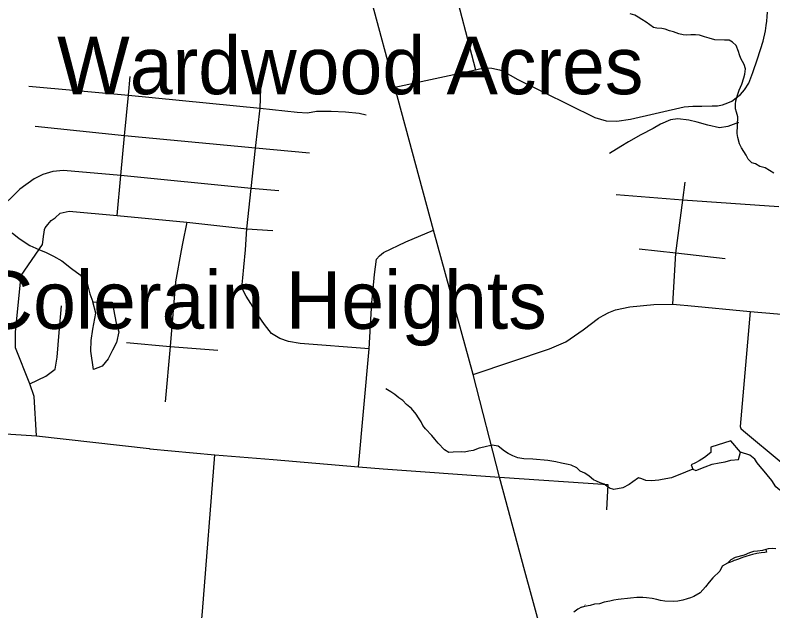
# Model space of a CAD drawing. Extents: x 0 to 69.5, y -4.5 to 22.
# Drawn here: x 3.515 to 4.554, y 16.285 to 17.102 of the extents above; entities that cross this region are included whole.
import ezdxf

# ---------------------------------------------------------------- set-up
doc = ezdxf.new("R2010")
doc.units = 0
for name, color, linetype in [('GM_X_County_Road', 7, 'Continuous'), ('GM_X_Minor_Lake', 7, 'Continuous'), ('GM_X_Minor_River', 7, 'Continuous'), ('GM_X_Township_Subdivision', 7, 'Continuous'), ('GM_X_Unincorporated_Text', 7, 'Continuous'), ('GM_X_US_Route', 7, 'Continuous')]:
    doc.layers.add(name, color=color, linetype=linetype)

msp = doc.modelspace()

# ---------------------------------------------------------------- linework, layer by layer
at = {"layer": 'GM_X_County_Road'}
for points in [[(4.1431, 16.6089), (4.2477, 16.644), (4.27, 16.6535), (4.294, 16.6701), (4.3151, 16.6862), (4.3212, 16.6898), (4.3294, 16.6938), (4.3383, 16.6974), (4.3582, 16.7015), (4.3907, 16.7048), (4.417, 16.7053), (4.427, 16.7043), (4.4376, 16.7033), (4.5229, 16.6954), (4.6194, 16.6869)], [(3.0077, 16.6072), (3.0199, 16.6034), (3.2263, 16.5685), (3.2928, 16.5595), (3.3237, 16.5541), (3.3826, 16.5464), (3.4363, 16.5348), (3.4732, 16.5304), (3.5089, 16.527), (3.5443, 16.5245), (3.6987, 16.5072), (3.6996, 16.5071)], [(3.6996, 16.5071), (3.7888, 16.4987), (3.8689, 16.4921)], [(3.6274, 15.5008), (3.6334, 15.5983), (3.6428, 15.6844), (3.6442, 15.6947), (3.6526, 15.7123), (3.6907, 15.7752), (3.6948, 15.7884), (3.6964, 15.8066), (3.7002, 15.8416), (3.7057, 15.8918), (3.7083, 15.9035), (3.7269, 15.9403), (3.7414, 15.9828), (3.7462, 16.0207), (3.7514, 16.0744), (3.7681, 16.2443), (3.7721, 16.2837), (3.7888, 16.4987)], [(3.8689, 16.4921), (3.869, 16.4921), (3.986, 16.4824), (4.0195, 16.4796), (4.1794, 16.4679)]]:
    msp.add_lwpolyline(points, dxfattribs=at)
at = {"layer": 'GM_X_Minor_Lake'}
for points in [[(3.6224, 16.6158), (3.6187, 16.6406), (3.6194, 16.6554), (3.6216, 16.6709), (3.6255, 16.6928), (3.6218, 16.7084)], [(3.6218, 16.7084), (3.6479, 16.7079), (3.6534, 16.6793), (3.6573, 16.6674), (3.6539, 16.6527), (3.6487, 16.6422), (3.6424, 16.6302), (3.6342, 16.6201), (3.6223, 16.6158)], [(4.5098, 16.5021), (4.4963, 16.5177), (4.4692, 16.5092), (4.469, 16.502), (4.4605, 16.495), (4.4532, 16.4906), (4.4482, 16.4877), (4.442, 16.4848), (4.4446, 16.479), (4.4483, 16.4774), (4.4613, 16.4821), (4.4709, 16.486), (4.4805, 16.4877), (4.4888, 16.489), (4.4965, 16.4912)], [(4.4965, 16.4912), (4.507, 16.4921), (4.5098, 16.5021)]]:
    msp.add_lwpolyline(points, dxfattribs=at)
at = {"layer": 'GM_X_Minor_River'}
for points in [[(4.5556, 16.8851), (4.5436, 16.8923), (4.5364, 16.8941), (4.5304, 16.8977), (4.5255, 16.8993), (4.5203, 16.904), (4.5175, 16.9098), (4.5109, 16.9195), (4.5084, 16.9253), (4.5063, 16.9337), (4.5053, 16.9391), (4.506, 16.9623), (4.5042, 16.9685), (4.5028, 16.9731), (4.503, 16.9795), (4.5035, 16.9841), (4.5056, 16.992), (4.5081, 16.9988), (4.5114, 17.0071), (4.5143, 17.0158), (4.5159, 17.0207), (4.5165, 17.0279), (4.5147, 17.034), (4.5104, 17.0422), (4.5083, 17.0472), (4.5072, 17.0518), (4.504, 17.0602), (4.4988, 17.0646), (4.4944, 17.0674), (4.4879, 17.0672), (4.4746, 17.0679), (4.467, 17.07), (4.4602, 17.0717), (4.4535, 17.0742), (4.4482, 17.0747), (4.4417, 17.0745), (4.4356, 17.0743), (4.431, 17.0745), (4.425, 17.0762), (4.4178, 17.0786), (4.4126, 17.0803), (4.4065, 17.0824), (4.402, 17.0833), (4.3952, 17.0838), (4.3906, 17.0847), (4.3806, 17.0919), (4.3746, 17.0958), (4.3693, 17.0987), (4.3648, 17.1014), (4.3584, 17.1035)], [(4.5057, 16.9543), (4.5072, 16.9546), (4.4926, 16.9489), (4.4808, 16.9469), (4.4649, 16.9507), (4.4502, 16.9548), (4.4388, 16.9574), (4.4237, 16.9593), (4.4138, 16.958), (4.3999, 16.9519), (4.3899, 16.9464), (4.373, 16.9373), (4.356, 16.9278), (4.3456, 16.9216), (4.3302, 16.9117)], [(3.5109, 16.8032), (3.5206, 16.7953), (3.5352, 16.7859), (3.5476, 16.7802), (3.5574, 16.7762), (3.5675, 16.771), (3.5791, 16.7646), (3.5922, 16.754), (3.6041, 16.7454), (3.6141, 16.7322), (3.6176, 16.7196), (3.6218, 16.7084)], [(4.4446, 16.479), (4.4342, 16.475), (4.4149, 16.4671), (4.4023, 16.4648), (4.3977, 16.4638), (4.3878, 16.4629), (4.3799, 16.4635), (4.3746, 16.4656), (4.3701, 16.4669), (4.3619, 16.4618), (4.3569, 16.4581), (4.3484, 16.4534), (4.3362, 16.4511), (4.3301, 16.4531), (4.323, 16.4583), (4.3174, 16.4603), (4.3125, 16.4624), (4.308, 16.4644), (4.3024, 16.4695), (4.2961, 16.4735), (4.2901, 16.4763), (4.2853, 16.481), (4.2777, 16.4843), (4.2732, 16.4852), (4.2645, 16.4873), (4.2566, 16.4891), (4.2456, 16.4909), (4.2251, 16.4926), (4.2126, 16.4934), (4.2042, 16.4947), (4.1975, 16.4972), (4.1911, 16.5004), (4.1862, 16.5036), (4.1773, 16.5107), (4.169, 16.5121), (4.1579, 16.5094), (4.1514, 16.5076), (4.1433, 16.5048), (4.1372, 16.5035), (4.1314, 16.5025), (4.1269, 16.5026), (4.1158, 16.5022), (4.1097, 16.5019), (4.1038, 16.5055), (4.0953, 16.5145), (4.0908, 16.52), (4.0864, 16.5251), (4.0779, 16.5344), (4.0743, 16.5391), (4.0717, 16.5441), (4.0684, 16.5492), (4.0652, 16.5546), (4.0585, 16.562), (4.0518, 16.5679), (4.0466, 16.573), (4.0411, 16.577), (4.0355, 16.5813), (4.0302, 16.5849), (4.0235, 16.5893)], [(4.6349, 16.4612), (4.6183, 16.4634), (4.6087, 16.4591), (4.5991, 16.4555), (4.5925, 16.4527), (4.5845, 16.4506), (4.576, 16.4482), (4.5692, 16.4495), (4.5635, 16.45), (4.5583, 16.4548), (4.5529, 16.4633), (4.5462, 16.4711), (4.5422, 16.4762), (4.5367, 16.4828), (4.5326, 16.4878), (4.5293, 16.4925), (4.5226, 16.498), (4.5097, 16.5022)], [(4.5443, 16.3688), (4.5455, 16.365), (4.543, 16.3647), (4.5382, 16.3641), (4.532, 16.3633), (4.5263, 16.3621), (4.5229, 16.3612), (4.5171, 16.3593), (4.5125, 16.3579), (4.5092, 16.3567), (4.5056, 16.3552), (4.5027, 16.354), (4.5012, 16.3536), (4.4985, 16.3524), (4.496, 16.3514), (4.4935, 16.3505), (4.4921, 16.3499)], [(4.54, 16.3677), (4.5331, 16.3667), (4.5274, 16.3661), (4.5221, 16.3644), (4.5147, 16.3612), (4.5025, 16.3577), (4.4967, 16.3548), (4.4921, 16.3499)], [(4.5443, 16.3688), (4.54, 16.3677)], [(4.5583, 16.3698), (4.553, 16.37), (4.5477, 16.3698), (4.5443, 16.3688)], [(4.4921, 16.3499), (4.4847, 16.346), (4.4814, 16.3392), (4.4717, 16.33), (4.4666, 16.324), (4.4618, 16.3177), (4.4544, 16.3095), (4.4459, 16.3044), (4.4413, 16.3027), (4.4367, 16.3013), (4.4305, 16.2995), (4.424, 16.2982), (4.4183, 16.2976), (4.4058, 16.2979), (4.4001, 16.2989), (4.3948, 16.3001), (4.3884, 16.3018), (4.3808, 16.3024), (4.3759, 16.303), (4.3675, 16.3032), (4.3587, 16.3023), (4.342, 16.3005), (4.3362, 16.2995), (4.3305, 16.2978), (4.3228, 16.2968), (4.3163, 16.2943), (4.3095, 16.2938), (4.3037, 16.292), (4.2957, 16.2907), (4.2913, 16.2894)], [(4.2965, 16.293), (4.2966, 16.2923)], [(4.2917, 16.2899), (4.2868, 16.2868), (4.281, 16.2831)]]:
    msp.add_lwpolyline(points, dxfattribs=at)
at = {"layer": 'GM_X_Township_Subdivision'}
for points in [[(4.2504, 17.246), (4.2399, 17.2463), (4.2209, 17.2479), (4.2, 17.2504), (4.1444, 17.2619), (4.1342, 17.2617), (4.1233, 17.2587), (4.1133, 17.2519), (4.1072, 17.2448), (4.1016, 17.2378), (4.098, 17.2281), (4.0972, 17.2166), (4.1007, 17.2009), (4.1059, 17.1806), (4.1093, 17.1652), (4.1138, 17.1512), (4.1464, 17.0268)], [(4.5267, 17.0228), (4.5332, 17.0419), (4.5407, 17.066), (4.5441, 17.0801), (4.5451, 17.0873), (4.5458, 17.0934), (4.5465, 17.0999), (4.5469, 17.1055)], [(4.0359, 17.0028), (4.1464, 17.0268), (4.1519, 17.0281)], [(4.1519, 17.0281), (4.1588, 17.0296), (4.162, 17.0296), (4.1688, 17.0289), (4.1794, 17.0268), (4.1835, 17.0251), (4.2044, 17.0136), (4.31, 16.9611), (4.3256, 16.9565), (4.3403, 16.9561), (4.3591, 16.9591), (4.4325, 16.9761), (4.4446, 16.9767), (4.4568, 16.9769), (4.4711, 16.9771), (4.4782, 16.9773), (4.4849, 16.9788), (4.4925, 16.9813), (4.498, 16.9837), (4.5039, 16.9882), (4.5096, 16.993), (4.5154, 16.9992), (4.5212, 17.0085), (4.5267, 17.0228)], [(3.6551, 16.8268), (3.6602, 16.8815), (3.6648, 16.9362), (3.6704, 16.9918), (3.6728, 17.0173)], [(3.5337, 17.0043), (3.6704, 16.9918), (3.851, 16.9739), (3.9019, 16.9687), (3.9161, 16.9677), (3.9282, 16.9699), (3.9484, 16.9699), (3.968, 16.969), (3.9869, 16.9674), (3.9965, 16.9649)], [(4.0003, 16.6438), (3.9059, 16.6515), (3.8901, 16.6543), (3.878, 16.658), (3.8668, 16.6649), (3.8569, 16.6776), (3.8426, 16.6978), (3.8383, 16.7064), (3.8317, 16.7164), (3.8261, 16.7279), (3.8274, 16.7415), (3.8286, 16.7561), (3.8308, 16.78), (3.8327, 16.8085), (3.8386, 16.8639), (3.8445, 16.9193), (3.851, 16.9739), (3.8519, 17.0009)], [(3.9186, 16.9122), (3.8445, 16.9193), (3.6648, 16.9362), (3.5425, 16.9491)], [(3.8766, 16.8608), (3.8386, 16.8639), (3.6602, 16.8815), (3.5812, 16.8884), (3.5665, 16.887), (3.553, 16.8832), (3.541, 16.877), (3.5216, 16.8628), (3.4605, 16.8035), (3.4221, 16.7604), (3.3897, 16.7285), (3.3838, 16.7214), (3.3793, 16.711), (3.3779, 16.6956), (3.3748, 16.6696), (3.3712, 16.6447), (3.371, 16.6339), (3.3731, 16.6233), (3.3815, 16.607), (3.3861, 16.5965), (3.388, 16.5857), (3.3826, 16.5464)], [(4.417, 16.7053), (4.421, 16.7752), (4.4308, 16.8481), (4.434, 16.8724)], [(4.5621, 16.8386), (4.4308, 16.8481), (4.3393, 16.855)], [(3.5546, 16.8011), (3.555, 16.8037), (3.5553, 16.8076), (3.5562, 16.8098), (3.5597, 16.8147), (3.5644, 16.8199), (3.5698, 16.8235), (3.5769, 16.8299), (3.5893, 16.833), (3.6551, 16.8268), (3.7507, 16.8176), (3.8327, 16.8085), (3.8684, 16.8061)], [(3.7507, 16.8176), (3.7446, 16.7885)], [(4.0044, 16.7081), (4.0046, 16.7116), (4.0079, 16.7459), (4.0104, 16.7671), (4.0145, 16.7716), (4.02, 16.7762), (4.0507, 16.7906), (4.0889, 16.8066)], [(3.5443, 16.5245), (3.5409, 16.5785), (3.535, 16.5962), (3.5154, 16.6452), (3.5157, 16.6673), (3.5235, 16.7448), (3.5527, 16.787), (3.5546, 16.8011)], [(3.7446, 16.7885), (3.7426, 16.7791), (3.7348, 16.7357), (3.7274, 16.6472), (3.7209, 16.5715)], [(4.4889, 16.7676), (4.421, 16.7752), (4.3708, 16.7808)], [(3.986, 16.4824), (4.0003, 16.6438), (4.0044, 16.7081)], [(3.535, 16.5962), (3.557, 16.6066), (3.5697, 16.6161), (3.5728, 16.6328), (3.5756, 16.6663), (3.5787, 16.703)], [(4.5229, 16.6954), (4.5093, 16.5377), (4.51, 16.5346), (4.514, 16.5314), (4.5654, 16.4888), (4.5695, 16.486), (4.5759, 16.4851), (4.6004, 16.488), (4.6411, 16.4852), (4.6505, 16.4838)], [(3.6678, 16.6528), (3.7274, 16.6472), (3.7929, 16.6423)], [(4.1794, 16.4679), (4.3279, 16.4578), (4.3259, 16.4234)]]:
    msp.add_lwpolyline(points, dxfattribs=at)
at = {"layer": 'GM_X_US_Route'}
msp.add_lwpolyline([(4.347, 15.8571), (4.343, 15.8718), (4.3094, 15.9915), (4.3082, 15.9958), (4.2961, 16.0399), (4.2826, 16.089), (4.2509, 16.204), (4.2124, 16.3441), (4.1884, 16.4342), (4.1794, 16.4679), (4.1431, 16.6089), (4.0889, 16.8066), (4.0359, 17.0028), (4.0043, 17.1198), (3.9604, 17.2824), (3.9324, 17.3858)], dxfattribs=at)

# ---------------------------------------------------------------- texts
at = {"layer": 'GM_X_Unincorporated_Text'}
for s, p in [('Wardwood Acres', (3.5725, 16.9932)), ('Colerain Heights', (3.4634, 16.6715))]:
    msp.add_text(s, height=0.078977, rotation=0, dxfattribs=at).set_placement(p)

doc.saveas('drawing.dxf')
